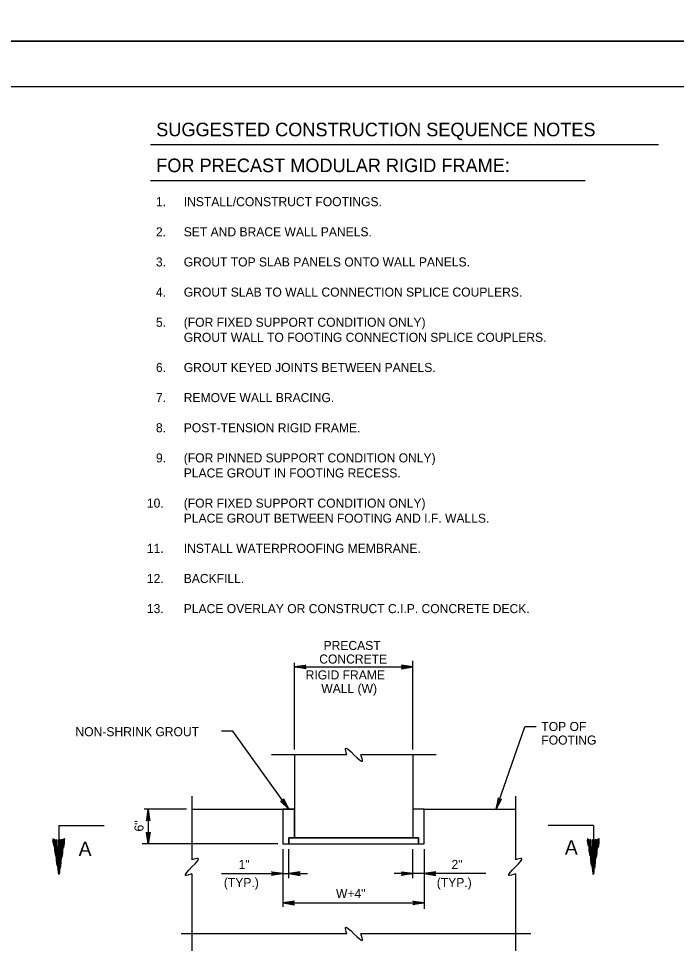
# Model space of a CAD drawing. Extents: x 641328 to 643024, y 298283 to 300065.
# Drawn here: x 641682.8 to 641901, y 299168.4 to 299478.8 of the extents above; entities that cross this region are included whole.
import ezdxf

# ---------------------------------------------------------------- set-up
doc = ezdxf.new("R2010")
doc.units = 0
doc.layers.add('2', color=7, linetype='Continuous')
doc.layers.add('PLT-BNDY', color=7, linetype='Continuous')

msp = doc.modelspace()

# ---------------------------------------------------------------- linework, layer by layer
at = {"layer": '2'}
for p, q in [((641367.51, 299456.3), (642153.5, 299456.3)), ((641726.47, 299437.02), (641895.07, 299437.02)), ((641726.47, 299425.13), (641870.77, 299425.13)), ((641813.54, 299236.37), (641813.54, 299265.77)), ((641774.26, 299236.37), (641774.26, 299265.14)), ((641774.26, 299263.77), (641778.05, 299264.4)), ((641777.86, 299264.23), (641774.26, 299263.77)), ((641774.26, 299263.77), (641777.73, 299263.96)), ((641774.26, 299263.77), (641777.73, 299263.78)), ((641774.26, 299263.77), (641813.54, 299263.77)), ((641777.73, 299263.6), (641774.26, 299263.77)), ((641774.26, 299263.77), (641777.87, 299263.34)), ((641778.06, 299263.18), (641774.26, 299263.77)), ((641777.73, 299263.96), (641777.86, 299264.23)), ((641777.73, 299263.6), (641777.73, 299263.96)), ((641777.87, 299263.34), (641777.73, 299263.6)), ((641778.05, 299264.4), (641777.86, 299264.23)), ((641777.87, 299263.34), (641778.06, 299263.18)), ((641813.54, 299263.77), (641809.74, 299264.4)), ((641809.74, 299264.4), (641809.94, 299264.23)), ((641809.74, 299263.18), (641813.54, 299263.77)), ((641809.93, 299263.34), (641809.74, 299263.18)), ((641813.54, 299263.77), (641809.93, 299263.34)), ((641809.93, 299263.34), (641810.07, 299263.6)), ((641810.07, 299263.96), (641809.94, 299264.23)), ((641809.94, 299264.23), (641813.54, 299263.77)), ((641813.54, 299263.77), (641810.07, 299263.96)), ((641810.07, 299263.6), (641810.07, 299263.96)), ((641813.54, 299263.77), (641810.07, 299263.78)), ((641810.07, 299263.6), (641813.54, 299263.77)), ((641841.18, 299216.53), (641850.72, 299243.93)), ((641854.47, 299243.93), (641850.72, 299243.93)), ((641753.85, 299242.41), (641750.1, 299242.41)), ((641772.35, 299216.53), (641753.85, 299242.41)), ((641791.68, 299234.63), (641766.68, 299234.63)), ((641774.26, 299234.63), (641774.26, 299207.1)), ((641821.31, 299234.63), (641796.31, 299234.63)), ((641813.54, 299234.63), (641813.54, 299207.1)), ((641740.23, 299220.92), (641740.23, 299199.73)), ((641772.35, 299216.53), (641769.64, 299219.26)), ((641769.64, 299219.26), (641769.9, 299219.2)), ((641770.19, 299219.25), (641769.9, 299219.2)), ((641769.9, 299219.2), (641772.35, 299216.53)), ((641770.48, 299219.46), (641770.19, 299219.25)), ((641772.35, 299216.53), (641770.19, 299219.25)), ((641772.35, 299216.53), (641770.33, 299219.36)), ((641770.62, 299219.73), (641770.48, 299219.46)), ((641770.48, 299219.46), (641772.35, 299216.53)), ((641770.62, 299219.73), (641770.64, 299219.98)), ((641772.35, 299216.53), (641770.62, 299219.73)), ((641770.64, 299219.98), (641772.35, 299216.53)), ((641841.86, 299220.32), (641841.18, 299216.53)), ((641841.18, 299216.53), (641841.95, 299220.09)), ((641841.18, 299216.53), (641843.01, 299219.92)), ((641842.15, 299219.87), (641841.18, 299216.53)), ((641841.18, 299216.53), (641842.32, 299219.81)), ((641842.78, 299219.79), (641841.18, 299216.53)), ((641841.18, 299216.53), (641842.49, 299219.75)), ((641841.95, 299220.09), (641841.86, 299220.32)), ((641841.95, 299220.09), (641842.15, 299219.87)), ((641842.15, 299219.87), (641842.49, 299219.75)), ((641842.49, 299219.75), (641842.78, 299219.79)), ((641843.01, 299219.92), (641842.78, 299219.79)), ((641847.57, 299220.92), (641847.57, 299199.73)), ((641738.47, 299216.53), (641724.39, 299216.53)), ((641725.76, 299216.53), (641725.13, 299212.74)), ((641725.3, 299212.93), (641725.76, 299216.53)), ((641725.76, 299216.53), (641725.57, 299213.06)), ((641725.76, 299216.53), (641725.75, 299213.06)), ((641725.76, 299216.53), (641725.76, 299205.1)), ((641725.93, 299213.06), (641725.76, 299216.53)), ((641725.76, 299216.53), (641726.19, 299212.92)), ((641726.35, 299212.73), (641725.76, 299216.53)), ((641770.45, 299216.53), (641774.26, 299216.53)), ((641774.26, 299207.1), (641774.26, 299216.53)), ((641817.35, 299216.53), (641813.54, 299216.53)), ((641817.35, 299216.53), (641813.54, 299216.53)), ((641813.54, 299216.53), (641813.54, 299207.1)), ((641725.13, 299212.74), (641725.3, 299212.93)), ((641725.57, 299213.06), (641725.3, 299212.93)), ((641725.93, 299213.06), (641725.57, 299213.06)), ((641726.19, 299212.92), (641725.93, 299213.06)), ((641726.19, 299212.92), (641726.35, 299212.73)), ((641696.03, 299211.14), (641711.06, 299211.14)), ((641696.03, 299211.14), (641696.03, 299196.11)), ((641873.48, 299211.14), (641858.45, 299211.14)), ((641873.48, 299211.14), (641873.48, 299196.11)), ((641725.76, 299205.1), (641725.13, 299208.9)), ((641725.13, 299208.9), (641725.3, 299208.7)), ((641725.57, 299208.57), (641725.3, 299208.7)), ((641725.3, 299208.7), (641725.76, 299205.1)), ((641725.93, 299208.58), (641725.57, 299208.57)), ((641725.76, 299205.1), (641725.57, 299208.57)), ((641725.76, 299205.1), (641725.75, 299208.58)), ((641726.35, 299208.9), (641725.76, 299205.1)), ((641725.76, 299205.1), (641726.19, 299208.71)), ((641725.93, 299208.58), (641725.76, 299205.1)), ((641726.19, 299208.71), (641725.93, 299208.58)), ((641726.19, 299208.71), (641726.35, 299208.9)), ((641774.26, 299207.1), (641813.54, 299207.1)), ((641813.54, 299207.1), (641815.44, 299207.1)), ((641815.44, 299207.1), (641815.44, 299205.1)), ((641768.71, 299205.1), (641723.76, 299205.1)), ((641770.45, 299203.35), (641770.45, 299184.16)), ((641772.35, 299193.71), (641772.35, 299203.35)), ((641813.54, 299193.71), (641813.54, 299203.35)), ((641817.35, 299203.35), (641817.35, 299183.53)), ((641740.23, 299195.11), (641740.23, 299169.62)), ((641750.02, 299195.26), (641770.45, 299195.26)), ((641766.84, 299195.69), (641766.65, 299195.85)), ((641766.65, 299195.85), (641770.45, 299195.26)), ((641770.45, 299195.26), (641766.65, 299194.63)), ((641766.65, 299194.63), (641766.85, 299194.8)), ((641766.84, 299195.69), (641766.98, 299195.43)), ((641770.45, 299195.26), (641766.84, 299195.69)), ((641766.85, 299194.8), (641770.45, 299195.26)), ((641766.98, 299195.06), (641766.85, 299194.8)), ((641766.98, 299195.43), (641770.45, 299195.26)), ((641766.98, 299195.43), (641766.98, 299195.06)), ((641770.45, 299195.26), (641766.98, 299195.06)), ((641770.45, 299195.26), (641766.98, 299195.24)), ((641770.45, 299195.26), (641778.54, 299195.26)), ((641776.16, 299195.85), (641772.35, 299195.26)), ((641772.35, 299195.26), (641775.96, 299195.69)), ((641775.83, 299195.43), (641772.35, 299195.26)), ((641772.35, 299195.26), (641775.82, 299195.06)), ((641775.95, 299194.8), (641772.35, 299195.26)), ((641772.35, 299195.26), (641776.15, 299194.63)), ((641772.35, 299195.26), (641775.83, 299195.24)), ((641775.83, 299195.43), (641775.82, 299195.06)), ((641775.82, 299195.06), (641775.95, 299194.8)), ((641775.96, 299195.69), (641775.83, 299195.43)), ((641776.15, 299194.63), (641775.95, 299194.8)), ((641775.96, 299195.69), (641776.16, 299195.85)), ((641817.35, 299195.26), (641807.35, 299195.26)), ((641809.93, 299195.69), (641809.74, 299195.85)), ((641809.74, 299195.85), (641813.54, 299195.26)), ((641813.54, 299195.26), (641809.74, 299194.63)), ((641809.74, 299194.63), (641809.94, 299194.8)), ((641809.93, 299195.69), (641810.07, 299195.43)), ((641813.54, 299195.26), (641809.93, 299195.69)), ((641809.94, 299194.8), (641813.54, 299195.26)), ((641810.07, 299195.06), (641809.94, 299194.8)), ((641810.07, 299195.43), (641813.54, 299195.26)), ((641810.07, 299195.43), (641810.07, 299195.06)), ((641813.54, 299195.26), (641810.07, 299195.06)), ((641813.54, 299195.26), (641810.07, 299195.24)), ((641821.15, 299195.85), (641817.35, 299195.26)), ((641817.35, 299195.26), (641820.96, 299195.69)), ((641820.82, 299195.43), (641817.35, 299195.26)), ((641817.35, 299195.26), (641820.82, 299195.06)), ((641820.95, 299194.8), (641817.35, 299195.26)), ((641817.35, 299195.26), (641821.14, 299194.63)), ((641817.35, 299195.26), (641820.82, 299195.24)), ((641837.78, 299195.26), (641817.35, 299195.26)), ((641820.96, 299195.69), (641820.82, 299195.43)), ((641820.82, 299195.43), (641820.82, 299195.06)), ((641820.82, 299195.06), (641820.95, 299194.8)), ((641821.14, 299194.63), (641820.95, 299194.8)), ((641820.96, 299195.69), (641821.15, 299195.85)), ((641847.57, 299195.11), (641847.57, 299169.62)), ((641774.25, 299186.12), (641770.45, 299185.53)), ((641770.45, 299185.53), (641774.06, 299185.96)), ((641773.92, 299185.7), (641770.45, 299185.53)), ((641770.45, 299185.53), (641817.35, 299185.53)), ((641770.45, 299185.53), (641773.92, 299185.34)), ((641774.05, 299185.07), (641770.45, 299185.53)), ((641770.45, 299185.53), (641774.24, 299184.9)), ((641770.45, 299185.53), (641773.92, 299185.52)), ((641774.06, 299185.96), (641773.92, 299185.7)), ((641773.92, 299185.7), (641773.92, 299185.34)), ((641773.92, 299185.34), (641774.05, 299185.07)), ((641774.24, 299184.9), (641774.05, 299185.07)), ((641774.06, 299185.96), (641774.25, 299186.12)), ((641813.74, 299185.96), (641813.55, 299186.12)), ((641813.55, 299186.12), (641817.35, 299185.53)), ((641817.35, 299185.53), (641813.55, 299184.9)), ((641813.55, 299184.9), (641813.75, 299185.07)), ((641813.74, 299185.96), (641813.88, 299185.7)), ((641817.35, 299185.53), (641813.74, 299185.96)), ((641813.75, 299185.07), (641817.35, 299185.53)), ((641813.88, 299185.34), (641813.75, 299185.07)), ((641813.88, 299185.7), (641817.35, 299185.53)), ((641813.88, 299185.7), (641813.88, 299185.34)), ((641817.35, 299185.53), (641813.88, 299185.34)), ((641817.35, 299185.53), (641813.88, 299185.52)), ((641791.68, 299175.24), (641736.68, 299175.24)), ((641852.73, 299175.24), (641796.31, 299175.24))]:
    msp.add_line(p, q, dxfattribs=at)
for points in [[(641740.23, 299216.53), (641770.45, 299216.53), (641770.45, 299205.1), (641817.35, 299205.1), (641817.35, 299216.53), (641847.57, 299216.53)], [(641770.45, 299216.53), (641770.45, 299205.1), (641772.35, 299205.1)], [(641774.26, 299216.53), (641772.35, 299216.53), (641770.45, 299216.53)], [(641815.44, 299205.1), (641817.35, 299205.1), (641817.35, 299216.53)], [(641694.11, 299206.84), (641696.09, 299194.96), (641698.07, 299206.84), (641697.87, 299206.64), (641697.87, 299205.45), (641697.67, 299203.87), (641697.67, 299206.64), (641697.27, 299206.44), (641697.27, 299202.09), (641697.08, 299200.5), (641697.08, 299206.44), (641696.68, 299206.44), (641696.68, 299198.92), (641696.48, 299196.94), (641696.48, 299206.44), (641696.28, 299206.44), (641696.28, 299195.55), (641696.09, 299194.96), (641695.89, 299196.54), (641695.89, 299206.25), (641695.69, 299206.44), (641695.49, 299197.93), (641695.29, 299199.51), (641695.29, 299206.44), (641695.1, 299206.44), (641695.1, 299201.1), (641694.7, 299202.88), (641694.7, 299206.44), (641694.5, 299206.64), (641694.5, 299204.27), (641694.11, 299206.05), (641694.3, 299206.64)], [(641772.35, 299205.1), (641772.35, 299207.1), (641774.26, 299207.1)], [(641871.45, 299206.84), (641873.43, 299194.96), (641875.41, 299206.84), (641875.21, 299206.64), (641875.21, 299205.45), (641875.01, 299203.87), (641875.01, 299206.64), (641874.61, 299206.44), (641874.61, 299202.09), (641874.42, 299200.5), (641874.42, 299206.44), (641874.02, 299206.44), (641874.02, 299198.92), (641873.82, 299196.94), (641873.82, 299206.44), (641873.62, 299206.44), (641873.62, 299195.55), (641873.43, 299194.96), (641873.23, 299196.54), (641873.23, 299206.25), (641873.03, 299206.44), (641872.83, 299197.93), (641872.63, 299199.51), (641872.63, 299206.44), (641872.44, 299206.44), (641872.44, 299201.1), (641872.04, 299202.88), (641872.04, 299206.44), (641871.84, 299206.64), (641871.84, 299204.27), (641871.45, 299206.05), (641871.64, 299206.64)]]:
    msp.add_lwpolyline(points, dxfattribs=at)
msp.add_lwpolyline([(641772.35, 299207.1), (641772.35, 299205.1), (641815.44, 299205.1), (641815.44, 299207.1)], close=True, dxfattribs=at)
for points in [[(641791.68, 299234.63), (641791.18, 299236.75), (641796.81, 299232.5), (641796.31, 299234.63)], [(641740.23, 299195.11), (641738.1, 299194.61), (641742.35, 299200.23), (641740.23, 299199.73)], [(641847.57, 299195.11), (641845.44, 299194.61), (641849.69, 299200.23), (641847.57, 299199.73)], [(641791.68, 299175.24), (641791.18, 299177.36), (641796.81, 299173.11), (641796.31, 299175.24)]]:
    msp.add_spline(points, degree=3, dxfattribs=at)
at = {"layer": 'PLT-BNDY'}
for points in [[(641327.51, 300065.3), (642168.51, 300065.3), (642168.51, 299471.3), (641327.51, 299471.3)], [(641327.51, 299471.3), (642168.51, 299471.3), (642168.51, 298877.3), (641327.51, 298877.3)]]:
    msp.add_lwpolyline(points, close=True, dxfattribs=at)

# ---------------------------------------------------------------- texts
at = {"layer": '2'}
for s, height, p in [('SUGGESTED CONSTRUCTION SEQUENCE NOTES', 4.5, (641728.39, 299439.8)), ('FOR PRECAST MODULAR RIGID FRAME:', 4.5, (641728.39, 299427.9)), ('1.', 3, (641728.29, 299416.61)), ('INSTALL/CONSTRUCT FOOTINGS.', 3, (641737.52, 299416.61)), ('2.', 3, (641728.29, 299406.61)), ('SET AND BRACE WALL PANELS.', 3, (641737.52, 299406.61)), ('3.', 3, (641728.29, 299396.61)), ('GROUT TOP SLAB PANELS ONTO WALL PANELS.', 3, (641737.52, 299396.61)), ('4.', 3, (641728.29, 299386.61)), ('GROUT SLAB TO WALL CONNECTION SPLICE COUPLERS.', 3, (641737.52, 299386.61)), ('5.', 3, (641728.29, 299376.61)), ('(FOR FIXED SUPPORT CONDITION ONLY)', 3, (641737.52, 299376.61)), ('GROUT WALL TO FOOTING CONNECTION SPLICE COUPLERS.', 3, (641737.52, 299371.61)), ('6.', 3, (641728.29, 299361.61)), ('GROUT KEYED JOINTS BETWEEN PANELS.', 3, (641737.52, 299361.61)), ('7.', 3, (641728.29, 299351.61)), ('REMOVE WALL BRACING.', 3, (641737.52, 299351.61)), ('8.', 3, (641728.29, 299341.61)), ('POST-TENSION RIGID FRAME.', 3, (641737.52, 299341.61)), ('9.', 3, (641728.29, 299331.61)), ('(FOR PINNED SUPPORT CONDITION ONLY)', 3, (641737.52, 299331.61)), ('PLACE GROUT IN FOOTING RECESS.', 3, (641737.52, 299326.61)), ('10.', 3, (641725.29, 299316.61)), ('(FOR FIXED SUPPORT CONDITION ONLY)', 3, (641737.52, 299316.61)), ('PLACE GROUT BETWEEN FOOTING AND I.F. WALLS.', 3, (641737.52, 299311.61)), ('11.', 3, (641725.29, 299301.61)), ('INSTALL WATERPROOFING MEMBRANE.', 3, (641737.52, 299301.61)), ('12.', 3, (641725.29, 299291.61)), ('BACKFILL.', 3, (641737.52, 299291.61)), ('13.', 3, (641725.29, 299281.61)), ('PLACE OVERLAY OR CONSTRUCT C.I.P. CONCRETE DECK.', 3, (641737.52, 299281.61)), ('PRECAST', 3, (641783.91, 299269.39)), ('CONCRETE', 3, (641782.48, 299264.89)), ('RIGID FRAME', 3, (641777.98, 299259.62)), ('WALL (W)', 3, (641783.16, 299255.12)), ('NON-SHRINK GROUT', 3, (641701.59, 299240.79)), ('TOP OF', 3, (641856.19, 299242.51)), ('FOOTING', 3, (641856.19, 299238.01)), ('1"', 3, (641755.72, 299196.76)), ('2"', 3, (641826.38, 299196.76)), ('(TYP.)', 3, (641750.83, 299190.76)), ('(TYP.)', 3, (641821.49, 299190.76)), ('W+4"', 3, (641788.05, 299187.11))]:
    msp.add_text(s, height=height, dxfattribs=at).set_placement(p)
for s, height, rotation, p in [('6"', 3, 90, (641724.18, 299209.17)), ('A', 4.8, 360, (641702.63, 299201.05)), ('A', 4.8, 360, (641863.98, 299201.49))]:
    msp.add_text(s, height=height, rotation=rotation, dxfattribs=at).set_placement(p)

doc.saveas('drawing.dxf')
